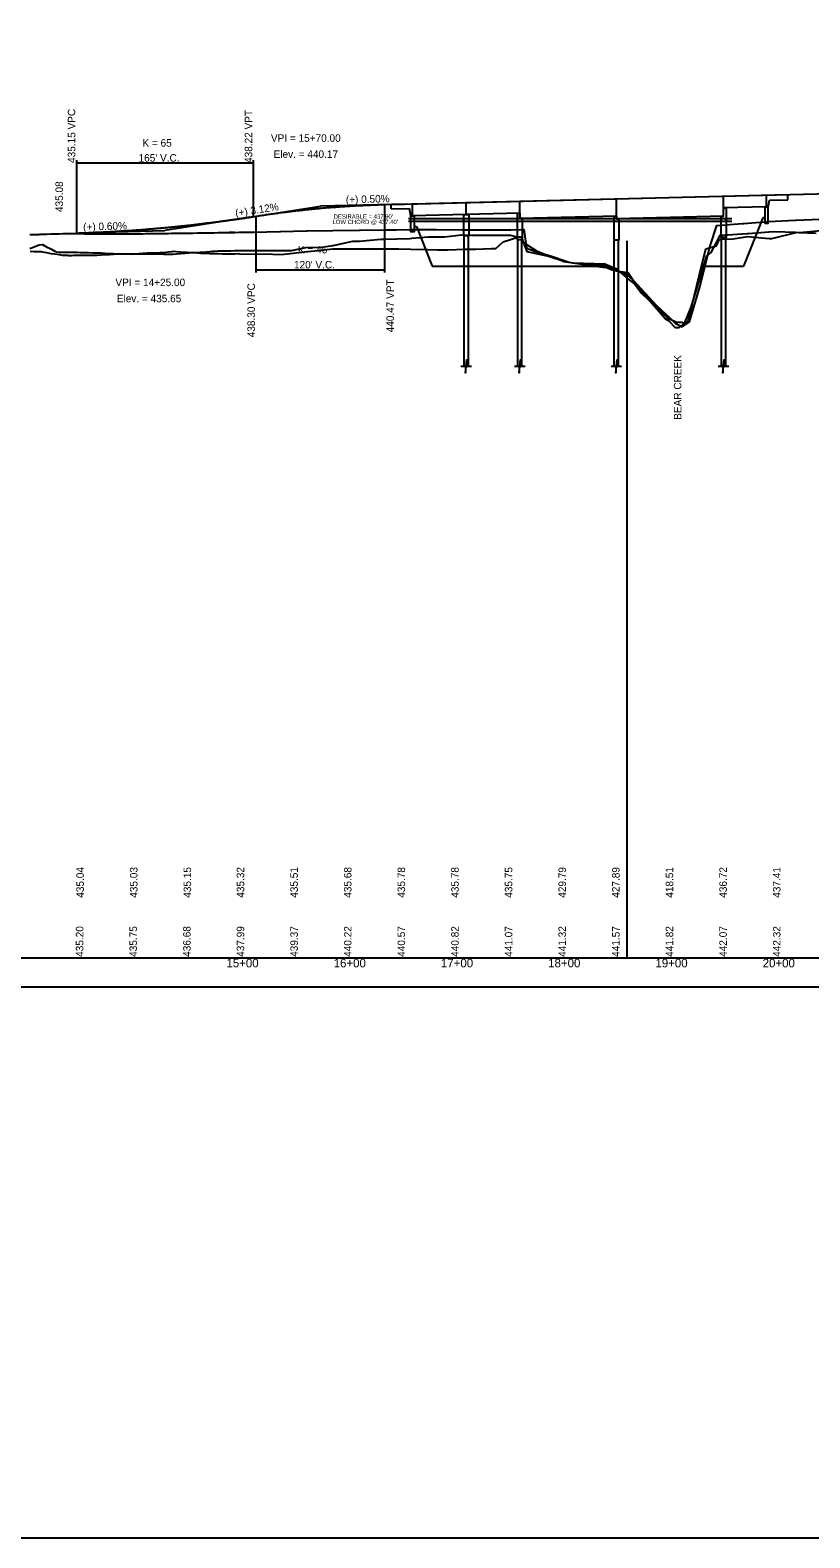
# Model space of a CAD drawing. Extents: x 2060925 to 2067820, y 1049917 to 1052773.
# Drawn here: x 2065139 to 2065865, y 1050573 to 1051979 of the extents above; entities that cross this region are included whole.
import ezdxf

# ---------------------------------------------------------------- set-up
doc = ezdxf.new("R2010")
doc.units = 0
for name, color, linetype in [('BR_CONCRETE', 7, 'Continuous'), ('BR_EXIST_GROUND_LT', 7, 'Continuous'), ('BR_EXIST_GROUND_RT', 7, 'Continuous'), ('BR_USER NOTES', 7, 'Continuous'), ('RD_DDB_GradeTX', 7, 'Continuous'), ('RD_DDB_Profile_EX', 7, 'Continuous'), ('RD_DDB_Profile_Lbl', 7, 'Continuous'), ('RD_DDB_Profile_PR', 7, 'Continuous'), ('RD_DDB_StaTX', 7, 'Continuous'), ('RD_DDB_StripGrade', 7, 'Continuous'), ('RD_DDB_VCLbl', 7, 'Continuous'), ('RD_GPK_Profile_Cell', 7, 'Continuous'), ('RD_SHT_IplotShp', 7, 'Continuous'), ('RD_SHT_ShtClip', 7, 'Continuous')]:
    doc.layers.add(name, color=color, linetype=linetype)

msp = doc.modelspace()

# ---------------------------------------------------------------- linework, layer by layer
at = {"layer": 'BR_CONCRETE'}
for p, q in [((2065475.1, 1051816.6), (2065845.1, 1051825.8)), ((2065845.1, 1051820.8), (2065845.1, 1051825.8)), ((2065475.1, 1051812.4), (2065475.1, 1051816.6)), ((2065475.1, 1051812.4), (2065492.2, 1051812.8)), ((2065493.6, 1051805.9), (2065492.2, 1051812.8)), ((2065495.1, 1051806.3), (2065495.1, 1051817.1)), ((2065545.1, 1051807.5), (2065545.1, 1051818.3)), ((2065595.1, 1051803.8), (2065595.1, 1051819.6)), ((2065685.1, 1051803.5), (2065685.1, 1051821.8)), ((2065785.1, 1051806), (2065785.1, 1051824.3)), ((2065785.1, 1051813.5), (2065825.1, 1051814.5)), ((2065825.1, 1051814.5), (2065825.1, 1051825.3)), ((2065825.1, 1051814.5), (2065825.1, 1051814.1)), ((2065826.6, 1051814.1), (2065827.9, 1051820.4)), ((2065827.9, 1051820.4), (2065845.1, 1051820.8)), ((2065495.1, 1051806.3), (2065595.1, 1051808.8)), ((2065495.1, 1051806.3), (2065495.1, 1051805.9)), ((2065545.1, 1051807.5), (2065545.1, 1051807.1)), ((2065595.1, 1051803.8), (2065685.1, 1051806)), ((2065685.1, 1051803.5), (2065785.1, 1051806)), ((2065821.6, 1051804.1), (2065803.6, 1051759)), ((2065823.6, 1051804.1), (2065821.6, 1051804.1)), ((2065496.6, 1051795.9), (2065498.6, 1051795.9)), ((2065498.6, 1051795.9), (2065513.4, 1051759)), ((2065543.1, 1051665.6), (2065543.1, 1051786.9)), ((2065547.1, 1051665.6), (2065547.1, 1051786.9)), ((2065783.1, 1051665.6), (2065783.1, 1051785.6)), ((2065787.1, 1051665.6), (2065787.1, 1051785.6)), ((2065593.1, 1051665.6), (2065593.1, 1051783.1)), ((2065597.1, 1051665.6), (2065597.1, 1051783.1)), ((2065683.1, 1051665.6), (2065683.1, 1051782.9)), ((2065687.1, 1051665.6), (2065687.1, 1051782.9)), ((2065513.4, 1051759), (2065675.8, 1051759)), ((2065767.7, 1051759), (2065803.6, 1051759))]:
    msp.add_line(p, q, dxfattribs=at)
for points in [[(2065785.1, 1051813.1), (2065787.4, 1051813.1), (2065787.4, 1051785.6), (2065782.9, 1051785.6), (2065782.9, 1051805.6), (2065785.1, 1051805.6)], [(2065826.6, 1051814.1), (2065823.6, 1051814.1), (2065823.6, 1051799.1), (2065826.6, 1051799.1)], [(2065493.6, 1051805.9), (2065496.6, 1051805.9), (2065496.6, 1051790.9), (2065493.6, 1051790.9)], [(2065545.1, 1051807.1), (2065547.4, 1051807.1), (2065547.4, 1051787.1), (2065542.9, 1051787.1), (2065542.9, 1051807.1), (2065545.1, 1051807.1)], [(2065595.1, 1051803.4), (2065597.4, 1051803.4), (2065597.4, 1051783.4), (2065592.9, 1051783.4), (2065592.9, 1051808.4), (2065595.1, 1051808.4)], [(2065685.1, 1051803.1), (2065687.4, 1051803.1), (2065687.4, 1051783.1), (2065682.9, 1051783.1), (2065682.9, 1051805.6), (2065685.1, 1051805.6)]]:
    msp.add_lwpolyline(points, close=True, dxfattribs=at)
for points in [[(2065540.1, 1051665.6), (2065544.5, 1051665.6), (2065544.5, 1051659.6), (2065545.7, 1051671.6), (2065545.7, 1051665.6), (2065550, 1051665.6)], [(2065590.1, 1051665.6), (2065594.5, 1051665.6), (2065594.5, 1051659.6), (2065595.7, 1051671.6), (2065595.7, 1051665.6), (2065600, 1051665.6)], [(2065680.1, 1051665.6), (2065684.5, 1051665.6), (2065684.5, 1051659.6), (2065685.7, 1051671.6), (2065685.7, 1051665.6), (2065690, 1051665.6)], [(2065780.1, 1051665.6), (2065784.5, 1051665.6), (2065784.5, 1051659.6), (2065785.7, 1051671.6), (2065785.7, 1051665.6), (2065790, 1051665.6)]]:
    msp.add_lwpolyline(points, dxfattribs=at)
at = {"layer": 'BR_EXIST_GROUND_LT'}
msp.add_line((2065695.2, 1051114), (2065695.2, 1051782.7), dxfattribs=at)
msp.add_lwpolyline([(2065138.4, 1051772.8), (2065142.1, 1051772.7), (2065146, 1051772.6), (2065148.7, 1051772.5), (2065149.9, 1051772.3), (2065153.8, 1051771.6), (2065157.7, 1051770.9), (2065161.6, 1051770.3), (2065165.5, 1051769.7), (2065168.3, 1051769.2), (2065169.4, 1051769.2), (2065173.5, 1051769.1), (2065174.5, 1051769), (2065177.2, 1051769), (2065179.2, 1051769.1), (2065181.1, 1051769.1), (2065185.1, 1051769.1), (2065189, 1051769.1), (2065192.9, 1051769.1), (2065196.8, 1051769.2), (2065199.1, 1051769.2), (2065200.7, 1051769.3), (2065204.6, 1051769.5), (2065206.6, 1051769.7), (2065208.5, 1051769.7), (2065212.4, 1051769.9), (2065216.3, 1051770.1), (2065220.2, 1051770.3), (2065223.6, 1051770.5), (2065224.1, 1051770.4), (2065228, 1051770.3), (2065231.9, 1051770.3), (2065233.6, 1051770.2), (2065235.8, 1051770.4), (2065239.7, 1051770.7), (2065243.6, 1051771), (2065247.5, 1051771.3), (2065248.3, 1051771.4), (2065251.4, 1051771.4), (2065255.3, 1051771.5), (2065259.3, 1051771.6), (2065260.4, 1051771.6), (2065263.2, 1051771.8), (2065267.1, 1051772.2), (2065271, 1051772.6), (2065272.6, 1051772.8), (2065274.9, 1051772.6), (2065278.8, 1051772.3), (2065282.7, 1051772.1), (2065284.9, 1051771.9), (2065286.6, 1051771.8), (2065290.5, 1051771.6), (2065294.4, 1051771.4), (2065297.3, 1051771.2), (2065298.3, 1051771.2), (2065302.2, 1051771), (2065306.1, 1051770.8), (2065310, 1051770.7), (2065311.7, 1051770.7), (2065313.9, 1051770.6), (2065317.8, 1051770.5), (2065322, 1051770.4), (2065323.1, 1051770.3), (2065325.6, 1051770.4), (2065329.5, 1051770.5), (2065333, 1051770.6), (2065333.5, 1051770.5), (2065348, 1051770.2), (2065356.6, 1051770.4), (2065372.6, 1051769.9), (2065381.1, 1051770.7), (2065397.5, 1051772.6), (2065407.1, 1051773.4), (2065420.8, 1051775), (2065432, 1051775), (2065445.8, 1051775.1), (2065456.6, 1051775.1), (2065468.4, 1051775.2), (2065482.3, 1051775), (2065493.4, 1051774.7), (2065509.4, 1051774.4), (2065518.4, 1051774.1), (2065519.1, 1051774.1), (2065527.6, 1051774.1), (2065544.1, 1051774.9), (2065553.7, 1051774.9), (2065568.7, 1051775.5), (2065572.6, 1051775.5), (2065579.6, 1051781.7), (2065594.2, 1051786.2), (2065596.4, 1051786.4), (2065601.6, 1051772.5), (2065621.7, 1051768.2), (2065634.2, 1051764.1), (2065636.2, 1051763.4), (2065672.4, 1051758), (2065675.1, 1051757.9), (2065681.2, 1051755.4), (2065684.8, 1051754.7), (2065695.7, 1051753.1), (2065704.3, 1051740.4), (2065704.7, 1051739.9), (2065730.9, 1051709.9), (2065734, 1051708), (2065739.9, 1051701.8), (2065743.8, 1051701.6), (2065752, 1051707.5), (2065762.9, 1051752.3), (2065768.6, 1051775), (2065778.5, 1051777.9), (2065781, 1051783.4), (2065782.4, 1051784), (2065794, 1051784.4), (2065807.3, 1051786.5), (2065827.7, 1051784.6), (2065828.8, 1051784.7), (2065829.9, 1051784.8), (2065852.8, 1051790.2), (2065859.4, 1051790.7), (2065875.6, 1051792.2)], dxfattribs=at)
at = {"layer": 'BR_EXIST_GROUND_RT'}
msp.add_lwpolyline([(2065138.2, 1051775.8), (2065139.2, 1051775.8), (2065142.1, 1051776.9), (2065146, 1051778.4), (2065146.9, 1051778.8), (2065150, 1051779.1), (2065153.8, 1051777.1), (2065157.7, 1051775.1), (2065161.6, 1051773), (2065163.2, 1051772.2), (2065165.5, 1051772.1), (2065169.4, 1051772), (2065172.3, 1051771.9), (2065173.3, 1051771.9), (2065177.2, 1051771.9), (2065181.1, 1051771.9), (2065182, 1051771.9), (2065185.1, 1051771.8), (2065189, 1051771.7), (2065192.9, 1051771.6), (2065196.8, 1051771.5), (2065197.6, 1051771.4), (2065200.7, 1051771.4), (2065204.6, 1051771.3), (2065208.2, 1051771.1), (2065208.5, 1051771.1), (2065212.4, 1051770.9), (2065216.3, 1051770.7), (2065220.2, 1051770.4), (2065222.6, 1051770.3), (2065224.1, 1051770.3), (2065228, 1051770.4), (2065231.9, 1051770.4), (2065232.8, 1051770.4), (2065235.8, 1051770.5), (2065239.7, 1051770.5), (2065243.6, 1051770.5), (2065247.5, 1051770.5), (2065247.9, 1051770.5), (2065251.4, 1051770.5), (2065255.3, 1051770.4), (2065256.7, 1051770.4), (2065259.3, 1051770.3), (2065263.2, 1051770.2), (2065267.1, 1051770.1), (2065271, 1051770), (2065271.8, 1051770), (2065274.9, 1051770.3), (2065278.8, 1051770.8), (2065281.8, 1051771.1), (2065282.7, 1051771.1), (2065286.6, 1051771.4), (2065290.5, 1051771.6), (2065294.4, 1051771.8), (2065297, 1051772), (2065298.3, 1051772.1), (2065302.2, 1051772.4), (2065306.1, 1051772.7), (2065308, 1051772.9), (2065310, 1051772.9), (2065313.9, 1051773.1), (2065317.8, 1051773.2), (2065321.7, 1051773.2), (2065325.6, 1051773.3), (2065329.5, 1051773.4), (2065333.5, 1051773.5), (2065335.5, 1051773.5), (2065346.9, 1051773.4), (2065358.9, 1051773.5), (2065370.5, 1051773.5), (2065382.3, 1051773.6), (2065395.4, 1051776.4), (2065410.5, 1051776.6), (2065420.4, 1051778.3), (2065421, 1051778.3), (2065439.4, 1051782.1), (2065445.6, 1051782.4), (2065465.5, 1051784), (2065466.8, 1051784), (2065468.3, 1051784), (2065492.5, 1051784.8), (2065494.5, 1051785), (2065509.9, 1051786.3), (2065517.1, 1051786.3), (2065524.7, 1051786.3), (2065540.8, 1051788.1), (2065549, 1051787.9), (2065565.8, 1051787.9), (2065573.9, 1051787.7), (2065586.5, 1051787.8), (2065593.6, 1051786), (2065596.7, 1051786.4), (2065598, 1051781.4), (2065610.7, 1051773.2), (2065613.6, 1051772.1), (2065618.5, 1051770.2), (2065622.6, 1051768.9), (2065641.2, 1051762.7), (2065644.3, 1051762.2), (2065674.3, 1051761.1), (2065684.5, 1051756.8), (2065699.1, 1051744.2), (2065702.1, 1051742.4), (2065708.4, 1051733.8), (2065732.8, 1051710.7), (2065740, 1051707.2), (2065740.8, 1051706.8), (2065742.9, 1051706.8), (2065746, 1051706.7), (2065748.6, 1051705.4), (2065754.9, 1051720.7), (2065769.3, 1051768.7), (2065773.6, 1051771.8), (2065780.6, 1051785), (2065781.8, 1051787.8), (2065784.2, 1051787.8), (2065807, 1051789.4), (2065808.4, 1051789.5), (2065827.4, 1051790.9), (2065832.6, 1051791.2), (2065852.2, 1051790.5), (2065855.3, 1051790.3), (2065871.3, 1051789.7)], dxfattribs=at)
at = {"layer": 'BR_USER NOTES'}
for p, q in [((2065491.2, 1051803.5), (2065792.7, 1051803.5)), ((2065491.2, 1051801), (2065792.7, 1051801)), ((2065329.1, 1051790.4), (2065324.1, 1051790.3))]:
    msp.add_line(p, q, dxfattribs=at)
at = {"layer": 'RD_DDB_GradeTX'}
for p, q in [((2065330.1, 1051802.6), (2065409.1, 1051814.9)), ((2065489.1, 1051816.9), (2065409.1, 1051814.9)), ((2065343.2, 1051804.6), (2065264.1, 1051792.3)), ((2065184.2, 1051789.9), (2065264.1, 1051792.3))]:
    msp.add_line(p, q, dxfattribs=at)
at = {"layer": 'RD_DDB_Profile_EX'}
msp.add_lwpolyline([(2065138.2, 1051788.4), (2065142.1, 1051788.5), (2065146, 1051788.6), (2065146.6, 1051788.6), (2065147.6, 1051788.7), (2065149.9, 1051788.7), (2065153.8, 1051788.8), (2065157.7, 1051789), (2065161.6, 1051789.1), (2065165.5, 1051789.2), (2065169.4, 1051789.3), (2065171.8, 1051789.4), (2065172.3, 1051789.4), (2065173.3, 1051789.4), (2065177.2, 1051789.4), (2065181.1, 1051789.3), (2065185.1, 1051789.3), (2065189, 1051789.2), (2065192.9, 1051789.2), (2065195.9, 1051789.2), (2065196.8, 1051789.2), (2065197.3, 1051789.2), (2065200.7, 1051789.2), (2065204.6, 1051789.1), (2065208.5, 1051789.1), (2065212.4, 1051789.1), (2065216.3, 1051789), (2065220.2, 1051789), (2065220.6, 1051789), (2065222.4, 1051789), (2065223.1, 1051789), (2065224.1, 1051789), (2065228, 1051789), (2065231.9, 1051789.1), (2065235.8, 1051789.1), (2065239.7, 1051789.2), (2065243.6, 1051789.2), (2065246.1, 1051789.3), (2065247.5, 1051789.3), (2065248.1, 1051789.3), (2065251.4, 1051789.3), (2065255.3, 1051789.4), (2065259.3, 1051789.4), (2065263.2, 1051789.5), (2065267.1, 1051789.5), (2065270.4, 1051789.6), (2065271, 1051789.6), (2065271.8, 1051789.6), (2065274.9, 1051789.6), (2065278.8, 1051789.6), (2065282.7, 1051789.7), (2065286.6, 1051789.7), (2065290.5, 1051789.8), (2065294.4, 1051789.9), (2065295.5, 1051789.9), (2065296.8, 1051789.9), (2065298.3, 1051789.9), (2065302.2, 1051790), (2065306.1, 1051790), (2065310, 1051790.1), (2065313.9, 1051790.2), (2065317.8, 1051790.2), (2065322, 1051790.3), (2065325.6, 1051790.4), (2065329.5, 1051790.4), (2065333.5, 1051790.5), (2065341.3, 1051790.7), (2065347.1, 1051790.8), (2065371.2, 1051791.3), (2065371.8, 1051791.3), (2065396.2, 1051791.8), (2065396.8, 1051791.8), (2065420.7, 1051792.2), (2065445.3, 1051792.5), (2065445.7, 1051792.5), (2065446.1, 1051792.5), (2065469, 1051792.8), (2065480.1, 1051792.9), (2065494, 1051793), (2065517.4, 1051793.1), (2065541.4, 1051792.9), (2065542.4, 1051792.9), (2065566, 1051792.8), (2065567.4, 1051792.8), (2065585.3, 1051792.7), (2065586.6, 1051792.7), (2065597.8, 1051793), (2065598.7, 1051793), (2065601.4, 1051775.7), (2065608.1, 1051773.1), (2065628.4, 1051766.5), (2065638.7, 1051763.1), (2065658.4, 1051760.1), (2065674.7, 1051759.5), (2065694.8, 1051751.1), (2065700.9, 1051745.8), (2065722.6, 1051722.1), (2065735.4, 1051710.3), (2065740.4, 1051705.3), (2065743.1, 1051704.2), (2065746.4, 1051702.5), (2065753.2, 1051706.9), (2065762.8, 1051739.8), (2065772.5, 1051777.9), (2065778.9, 1051796.9), (2065802.8, 1051798.7), (2065803.9, 1051798.7), (2065826.5, 1051800.5), (2065827.4, 1051800.5), (2065851.7, 1051801.7), (2065852.4, 1051801.8), (2065852.8, 1051801.8), (2065875.2, 1051802.9)], dxfattribs=at)
at = {"layer": 'RD_DDB_Profile_PR'}
for p, q in [((2065469.1, 1051816.4), (2066006.6, 1051829.8)), ((2065346.6, 1051805.2), (2065349.1, 1051805.5)), ((2065169.1, 1051789.4), (2065181.6, 1051789.8))]:
    msp.add_line(p, q, dxfattribs=at)
for points in [[(2065349.1, 1051805.5), (2065351.5, 1051805.9), (2065353.9, 1051806.3), (2065356.3, 1051806.6), (2065358.7, 1051807), (2065361.1, 1051807.3), (2065363.5, 1051807.7), (2065365.9, 1051808), (2065368.3, 1051808.3), (2065370.7, 1051808.7), (2065373.1, 1051809), (2065375.5, 1051809.3), (2065377.9, 1051809.6), (2065380.3, 1051809.9), (2065382.7, 1051810.2), (2065385.1, 1051810.5), (2065387.5, 1051810.7), (2065389.9, 1051811), (2065392.3, 1051811.3), (2065394.7, 1051811.5), (2065397.1, 1051811.8), (2065399.5, 1051812), (2065401.9, 1051812.3), (2065404.3, 1051812.5), (2065406.7, 1051812.7), (2065409.1, 1051812.9), (2065411.5, 1051813.2), (2065413.9, 1051813.4), (2065416.3, 1051813.6), (2065418.7, 1051813.8), (2065421.1, 1051813.9), (2065423.5, 1051814.1), (2065425.9, 1051814.3), (2065428.3, 1051814.5), (2065430.7, 1051814.6), (2065433.1, 1051814.8), (2065435.5, 1051814.9), (2065437.9, 1051815.1), (2065440.3, 1051815.2), (2065442.7, 1051815.4), (2065445.1, 1051815.5), (2065447.5, 1051815.6), (2065449.9, 1051815.7), (2065452.3, 1051815.8), (2065454.7, 1051815.9), (2065457.1, 1051816), (2065459.5, 1051816.1), (2065461.9, 1051816.2), (2065464.3, 1051816.3), (2065466.7, 1051816.3), (2065469.1, 1051816.4)], [(2065181.6, 1051789.8), (2065184.9, 1051789.9), (2065188.2, 1051790), (2065191.5, 1051790.1), (2065194.8, 1051790.3), (2065198.1, 1051790.4), (2065201.4, 1051790.6), (2065204.7, 1051790.7), (2065208, 1051790.9), (2065211.3, 1051791), (2065214.6, 1051791.2), (2065217.9, 1051791.4), (2065221.2, 1051791.6), (2065224.5, 1051791.8), (2065227.8, 1051792), (2065231.1, 1051792.2), (2065234.4, 1051792.5), (2065237.7, 1051792.7), (2065241, 1051792.9), (2065244.3, 1051793.2), (2065247.6, 1051793.5), (2065250.9, 1051793.7), (2065254.2, 1051794), (2065257.5, 1051794.3), (2065260.8, 1051794.6), (2065264.1, 1051794.9), (2065267.4, 1051795.2), (2065270.7, 1051795.5), (2065274, 1051795.8), (2065277.3, 1051796.2), (2065280.6, 1051796.5), (2065283.9, 1051796.9), (2065287.2, 1051797.2), (2065290.5, 1051797.6), (2065293.8, 1051798), (2065297.1, 1051798.4), (2065300.4, 1051798.8), (2065303.7, 1051799.2), (2065307, 1051799.6), (2065310.3, 1051800), (2065313.6, 1051800.4), (2065316.9, 1051800.9), (2065320.2, 1051801.3), (2065323.5, 1051801.8), (2065326.8, 1051802.2), (2065330.1, 1051802.7), (2065333.4, 1051803.2), (2065336.7, 1051803.6), (2065340, 1051804.1), (2065343.3, 1051804.6), (2065346.6, 1051805.2)]]:
    msp.add_spline(points, degree=3, dxfattribs=at)
at = {"layer": 'RD_DDB_VCLbl'}
for p, q in [((2065181.6, 1051857.7), (2065181.6, 1051789.8)), ((2065181.6, 1051855.2), (2065346.6, 1051855.2)), ((2065346.6, 1051857.7), (2065346.6, 1051805.2)), ((2065469.1, 1051753), (2065469.1, 1051816.4)), ((2065349.1, 1051753), (2065349.1, 1051805.5)), ((2065349.1, 1051755.5), (2065469.1, 1051755.5))]:
    msp.add_line(p, q, dxfattribs=at)
at = {"layer": 'RD_GPK_Profile_Cell'}
msp.add_line((2064839.1, 1051114), (2067200.8, 1051114), dxfattribs=at)
at = {"layer": 'RD_SHT_IplotShp'}
msp.add_lwpolyline([(2064220, 1050573), (2067820, 1050573), (2067820, 1052773), (2064220, 1052773)], close=True, dxfattribs=at)
at = {"layer": 'RD_SHT_ShtClip'}
msp.add_lwpolyline([(2064734.6, 1052186.6), (2066534.6, 1052186.6), (2066534.6, 1051086.6), (2064734.6, 1051086.6)], close=True, dxfattribs=at)

# ---------------------------------------------------------------- texts
at = {"layer": 'BR_USER NOTES'}
for s, p in [("LOW CHORD @ 437.40'", (2065420.4, 1051798.2)), ("DESIRABLE = 437.90'", (2065421.5, 1051803.2))]:
    msp.add_text(s, height=4, dxfattribs=at).set_placement(p)
at = {"layer": 'RD_DDB_GradeTX'}
for s, rotation, p in [('(+) 0.50%', 1.4321, (2065432.9, 1051817.5)), ('(+) 3.12%', 8.8667, (2065330.3, 1051804.9)), ('(+) 0.60%', 1.7184, (2065188, 1051792))]:
    msp.add_text(s, height=7, rotation=rotation, dxfattribs=at).set_placement(p)
at = {"layer": 'RD_DDB_Profile_Lbl'}
for s, p in [('VPI = 15+70.00', (2065363, 1051874.9)), ('Elev. = 440.17', (2065365.5, 1051859.9)), ('VPI = 14+25.00', (2065218, 1051740.3)), ('Elev. = 435.65', (2065219.3, 1051725.3))]:
    msp.add_text(s, height=7, dxfattribs=at).set_placement(p)
for s, p in [('435.08', (2065169.1, 1051809.4)), ('BEAR CREEK', (2065745.7, 1051615.7))]:
    msp.add_text(s, height=7, rotation=90, dxfattribs=at).set_placement(p)
at = {"layer": 'RD_DDB_StaTX'}
for s, p in [('15+00', (2065321.5, 1051105)), ('16+00', (2065421.5, 1051105)), ('17+00', (2065521.5, 1051105)), ('18+00', (2065621.5, 1051105)), ('19+00', (2065721.5, 1051105)), ('20+00', (2065821.5, 1051105))]:
    msp.add_text(s, height=8, dxfattribs=at).set_placement(p)
at = {"layer": 'RD_DDB_StripGrade'}
for s, p in [('435.15 VPC', (2065180.6, 1051855.2)), ('438.22 VPT', (2065345.6, 1051855.2)), ('438.30 VPC', (2065348.1, 1051692.6)), ('440.47 VPT', (2065477.7, 1051697.2)), ('435.04', (2065188.6, 1051169.9)), ('435.03', (2065238.6, 1051169.9)), ('435.15', (2065288.6, 1051169.9)), ('435.32', (2065338.1, 1051169.9)), ('435.51', (2065388.1, 1051169.9)), ('435.68', (2065438.1, 1051169.9)), ('435.78', (2065488.1, 1051169.9)), ('435.78', (2065538.1, 1051169.9)), ('435.75', (2065588.1, 1051169.9)), ('429.79', (2065638.1, 1051169.9)), ('427.89', (2065688.1, 1051169.9)), ('418.51', (2065738.1, 1051169.9)), ('436.72', (2065788.1, 1051169.9)), ('437.41', (2065838.1, 1051169.9)), ('435.20', (2065188.1, 1051114.8)), ('435.75', (2065238.1, 1051114.8)), ('436.68', (2065288.1, 1051114.8)), ('437.99', (2065338.1, 1051114.8)), ('439.37', (2065388.1, 1051114.8)), ('440.22', (2065438.1, 1051114.8)), ('440.57', (2065488.1, 1051114.8)), ('440.82', (2065538.1, 1051114.8)), ('441.07', (2065588.1, 1051114.8)), ('441.32', (2065638.1, 1051114.8)), ('441.57', (2065688.1, 1051114.8)), ('441.82', (2065738.1, 1051114.8)), ('442.07', (2065788.1, 1051114.8)), ('442.32', (2065838.1, 1051114.8))]:
    msp.add_text(s, height=7, rotation=90, dxfattribs=at).set_placement(p)
at = {"layer": 'RD_DDB_VCLbl'}
for s, p in [('K = 65', (2065243.2, 1051870.4)), ("165' V.C.", (2065239.6, 1051856.4)), ('K = 46', (2065388.2, 1051770.8)), ("120' V.C.", (2065384.5, 1051756.8))]:
    msp.add_text(s, height=7, dxfattribs=at).set_placement(p)

doc.saveas('drawing.dxf')
